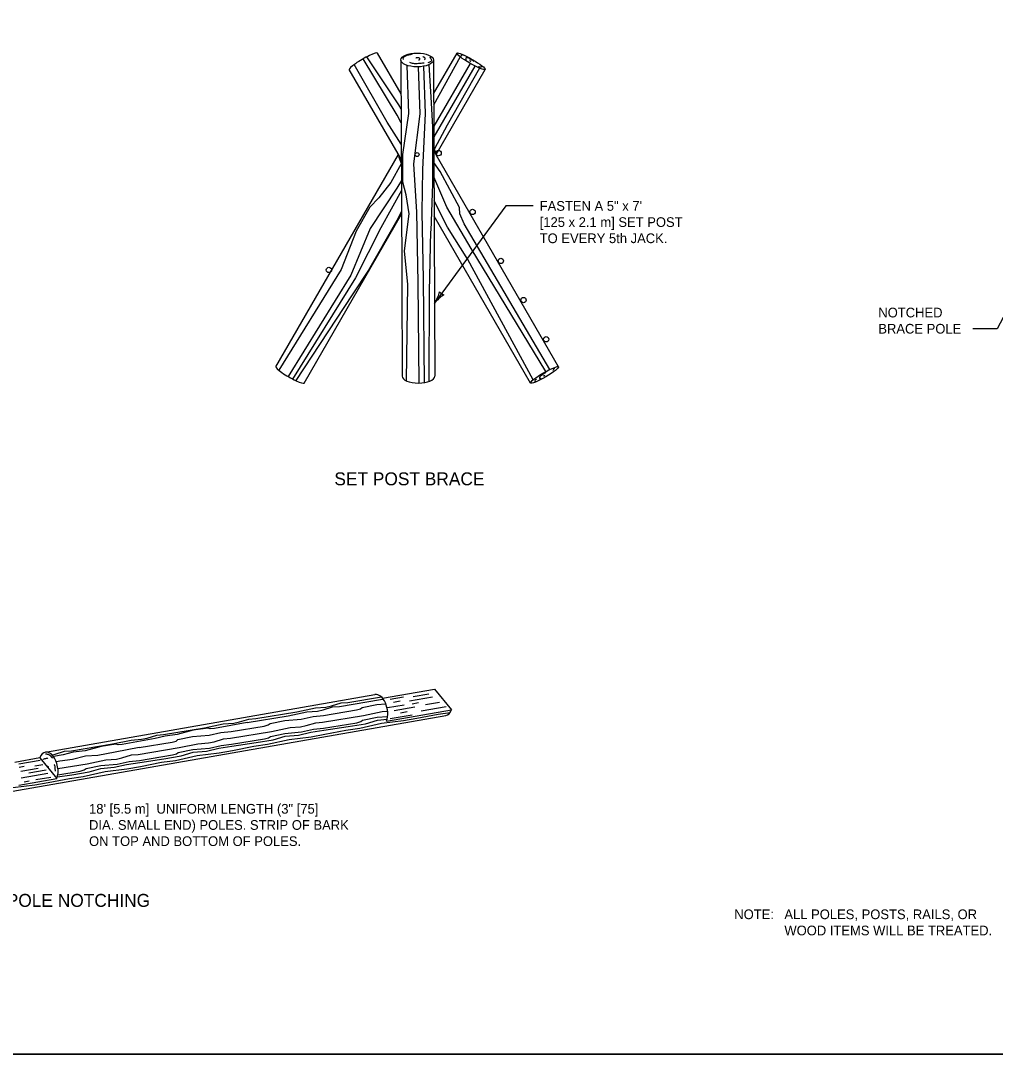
# Model space of a CAD drawing. Extents: x 49991.4 to 50021, y 49987.6 to 50011.4.
# Drawn here: x 50003.32 to 50009.35, y 49987.8 to 49994.19 of the extents above; entities that cross this region are included whole.
import ezdxf

# ---------------------------------------------------------------- set-up
doc = ezdxf.new("R2010")
doc.units = 0
for name, color, linetype in [('Level 1', 7, 'Continuous'), ('Level 2', 7, 'Continuous'), ('Level 3', 7, 'Continuous')]:
    doc.layers.add(name, color=color, linetype=linetype)

msp = doc.modelspace()

# ---------------------------------------------------------------- linework, layer by layer
at = {"layer": 'Level 1'}
for p, q in [((50005.6739, 49993.7368), (50005.5282, 49993.9891)), ((50005.875, 49993.737), (50006.0201, 49993.9885)), ((50005.6729, 49993.9457), (50005.6789, 49992.6324)), ((50005.874, 49993.9466), (50005.8788, 49992.8942)), ((50005.6557, 49993.3661), (50005.3543, 49993.8881)), ((50005.8904, 49993.3618), (50006.1944, 49993.8878)), ((50005.8766, 49993.3857), (50005.8933, 49993.3567)), ((50004.9005, 49992.049), (50005.6583, 49993.3616)), ((50005.6759, 49993.3309), (50005.6557, 49993.3661)), ((50006.6479, 49992.0498), (50005.8933, 49993.3567)), ((50005.0748, 49991.9487), (50005.6775, 49992.9928)), ((50006.474, 49991.9487), (50005.8784, 49992.9803)), ((50005.8785, 49992.8945), (50005.883, 49991.9911)), ((50005.6789, 49992.6324), (50005.6791, 49992.5534)), ((50005.6793, 49992.5688), (50005.6817, 49991.9911)), ((50003.4771, 49989.6671), (50005.5129, 49990.0228)), ((50005.5599, 49990.0012), (50005.8806, 49990.0572)), ((50005.6077, 49989.994), (50005.6902, 49990.0084)), ((50005.7266, 49989.9844), (50005.8681, 49990.0091)), ((50005.7483, 49990.0111), (50005.8449, 49990.028)), ((50005.8806, 49990.0572), (50005.9865, 49989.9297)), ((50005.5908, 49989.9425), (50005.6925, 49989.9603)), ((50005.6283, 49989.977), (50005.6688, 49989.984)), ((50005.6318, 49989.9254), (50005.7592, 49989.9476)), ((50005.7419, 49989.9667), (50005.7824, 49989.9738)), ((50005.7988, 49989.9229), (50005.9524, 49989.9497)), ((50005.8257, 49989.9616), (50005.9125, 49989.9768)), ((50000.9144, 49989.0139), (50005.951, 49989.8934)), ((50005.5849, 49989.8595), (50005.9865, 49989.9297)), ((50005.6076, 49989.8749), (50005.7433, 49989.8986)), ((50005.6714, 49989.9104), (50005.7118, 49989.9174)), ((50003.4416, 49989.6311), (50003.2869, 49989.6041)), ((50003.4436, 49989.6163), (50003.3119, 49989.5933)), ((50003.4416, 49989.6311), (50003.5478, 49989.5037)), ((50003.3445, 49989.5782), (50003.3151, 49989.5731)), ((50003.4314, 49989.5665), (50003.3243, 49989.5479)), ((50003.4812, 49989.5562), (50003.3745, 49989.5375)), ((50003.46, 49989.5896), (50003.411, 49989.5811)), ((50003.3119, 49989.4625), (50003.5478, 49989.5037)), ((50003.4907, 49989.5356), (50003.3277, 49989.5072)), ((50003.3757, 49989.4873), (50003.3464, 49989.4822)), ((50003.5108, 49989.5113), (50003.4181, 49989.4951))]:
    msp.add_line(p, q, dxfattribs=at)
msp.add_lwpolyline([(49999.3835, 49998.9992), (50016.7501, 49998.9992), (50016.7501, 49987.7988), (49999.3835, 49987.7988)], close=True, dxfattribs=at)
for points in [[(50005.6744, 49993.6448), (50005.6615, 49993.6702), (50005.4629, 49993.9662)], [(50006.0399, 49993.9658), (50005.8753, 49993.6669)], [(50005.6754, 49993.427), (50005.5886, 49993.5617), (50005.3837, 49993.9179)], [(50005.6748, 49993.5576), (50005.6504, 49993.6056), (50005.4401, 49993.9538)], [(50005.696, 49992.7666), (50005.7236, 49992.9951), (50005.7051, 49993.1132), (50005.6856, 49993.1918), (50005.6854, 49993.3619), (50005.7228, 49993.6147), (50005.7122, 49993.9129)], [(50005.7799, 49992.5686), (50005.7716, 49993.0065), (50005.7526, 49993.3054), (50005.7928, 49993.6145), (50005.7823, 49993.9043)], [(50005.8128, 49992.5913), (50005.8045, 49993.0062), (50005.8081, 49993.2697), (50005.8255, 49993.6148), (50005.8149, 49993.9079)], [(50005.8602, 49992.8906), (50005.8709, 49993.1807), (50005.871, 49993.5336), (50005.8605, 49993.7157), (50005.8476, 49993.9179)], [(50006.1021, 49993.9249), (50005.8759, 49993.537)], [(50006.1311, 49993.9091), (50005.8762, 49993.4717)], [(50006.1598, 49993.8956), (50005.9597, 49993.5429), (50005.8807, 49993.3964)], [(50005.6758, 49993.3047), (50005.6117, 49993.1883), (50005.5371, 49993.0949), (50005.4811, 49993.0362), (50005.3966, 49992.8886), (50005.3037, 49992.6506), (50004.9181, 49992.0285)], [(50006.5936, 49992.0328), (50006.0652, 49992.9326), (50006.0366, 49992.9963), (50006.0344, 49993.0354), (50005.9152, 49993.2571), (50005.8769, 49993.3119)], [(50005.6765, 49993.2023), (50005.6477, 49993.1544), (50005.4831, 49992.9044), (50005.3645, 49992.6161), (50004.9762, 49991.9895)], [(50006.5681, 49992.0195), (50006.107, 49992.782), (50005.9572, 49993.0356), (50005.8773, 49993.2241)], [(50005.6768, 49993.1391), (50005.5489, 49992.9078), (50005.3928, 49992.5995), (50005.0044, 49991.9738)], [(50006.4906, 49991.969), (50006.0865, 49992.7125), (50005.9612, 49992.9128), (50005.878, 49993.0767)], [(50005.6774, 49993.0111), (50005.6475, 49992.954), (50005.4726, 49992.6475), (50005.373, 49992.4946), (50005.0236, 49991.9641)], [(50005.8481, 49991.9593), (50005.8497, 49992.5145), (50005.8591, 49992.8883)], [(50005.7167, 49992.5577), (50005.696, 49992.7666)], [(50005.7074, 49991.9624), (50005.7167, 49992.5577)], [(50005.7855, 49991.9487), (50005.7799, 49992.5686)], [(50005.8183, 49991.9516), (50005.8128, 49992.5913)], [(50005.2935, 49989.9501), (50005.5467, 49989.9919), (50005.5643, 49989.9956)], [(50005.346, 49989.9745), (50005.5529, 49990.0086)], [(50004.724, 49989.8506), (50004.9771, 49989.8925), (50005.0923, 49989.9164), (50005.1577, 49989.9214), (50005.1923, 49989.9287), (50005.2511, 49989.9468), (50005.2935, 49989.9501)], [(50004.7765, 49989.8749), (50005.0296, 49989.9168), (50005.1448, 49989.9407), (50005.2101, 49989.9457), (50005.2448, 49989.953), (50005.3034, 49989.9711), (50005.346, 49989.9745)], [(50005.1942, 49989.8943), (50005.3984, 49989.9279), (50005.4231, 49989.9347), (50005.4345, 49989.9433), (50005.5246, 49989.9618), (50005.5801, 49989.9665)], [(50004.207, 49989.7756), (50004.4602, 49989.8173), (50004.5753, 49989.8414), (50004.6407, 49989.8463), (50004.6753, 49989.8535), (50004.7341, 49989.8717), (50004.7765, 49989.8749)], [(50004.6249, 49989.7949), (50004.8291, 49989.8285), (50004.8536, 49989.8354), (50004.8652, 49989.844), (50004.9553, 49989.8624), (50005.0576, 49989.871), (50005.1309, 49989.8878), (50005.1942, 49989.8943)], [(50005.1895, 49989.8524), (50005.4425, 49989.8942), (50005.5577, 49989.9181), (50005.5912, 49989.9207)], [(50005.1959, 49989.8153), (50005.4, 49989.8489), (50005.4248, 49989.8558), (50005.4362, 49989.8644), (50005.5264, 49989.8828), (50005.5913, 49989.8883)], [(50005.1981, 49989.8027), (50005.3481, 49989.8256), (50005.4544, 49989.8427), (50005.5281, 49989.865), (50005.5882, 49989.8705)], [(50005.2024, 49989.7773), (50005.3332, 49989.8034), (50005.4188, 49989.8152), (50005.5531, 49989.8456), (50005.6884, 49989.8622), (50005.7717, 49989.8768)], [(50005.7717, 49989.8768), (50005.9026, 49989.9029), (50005.9783, 49989.9132)], [(50004.724, 49989.8506), (50004.5206, 49989.8132), (50004.4949, 49989.8111), (50004.4814, 49989.8152), (50004.3903, 49989.802), (50004.2911, 49989.7756), (50004.2165, 49989.7665), (50004.1547, 49989.7511)], [(50004.6201, 49989.7529), (50004.8732, 49989.7946), (50004.9883, 49989.8187), (50005.0537, 49989.8236), (50005.0883, 49989.831), (50005.1472, 49989.849), (50005.1895, 49989.8524)], [(50004.6265, 49989.7158), (50004.8306, 49989.7494), (50004.8553, 49989.7563), (50004.8669, 49989.7648), (50004.957, 49989.7834), (50005.0592, 49989.792), (50005.1324, 49989.8088), (50005.1959, 49989.8153)], [(50004.1547, 49989.7511), (50003.9512, 49989.7136), (50003.9256, 49989.7116), (50003.9121, 49989.7157), (50003.821, 49989.7024), (50003.7218, 49989.676), (50003.6473, 49989.6668), (50003.5855, 49989.6515)], [(50003.6376, 49989.676), (50003.8907, 49989.7178), (50004.0059, 49989.7419), (50004.0712, 49989.7467), (50004.1059, 49989.7541), (50004.1646, 49989.7722), (50004.207, 49989.7756)], [(50004.0506, 49989.6533), (50004.3037, 49989.6952), (50004.4189, 49989.7192), (50004.4843, 49989.7241), (50004.519, 49989.7316), (50004.5777, 49989.7496), (50004.6201, 49989.7529)], [(50004.0556, 49989.6955), (50004.2597, 49989.729), (50004.2844, 49989.736), (50004.2958, 49989.7445), (50004.386, 49989.7631), (50004.4882, 49989.7717), (50004.5615, 49989.7884), (50004.6249, 49989.7949)], [(50004.6287, 49989.7032), (50004.7786, 49989.7261), (50004.885, 49989.7433), (50004.9588, 49989.7656), (50005.0409, 49989.773), (50005.117, 49989.7904), (50005.1981, 49989.8027)], [(50004.6331, 49989.6778), (50004.7639, 49989.7039), (50004.8495, 49989.7157), (50004.9838, 49989.7463), (50005.1189, 49989.7628), (50005.2024, 49989.7773)], [(50003.5179, 49989.6507), (50003.5365, 49989.6546), (50003.5952, 49989.6727), (50003.6376, 49989.676)], [(50004.0556, 49989.6955), (50003.9068, 49989.6661), (50003.801, 49989.6465), (50003.7241, 49989.6423), (50003.6442, 49989.6215), (50003.5667, 49989.612), (50003.5442, 49989.6075)], [(50004.0572, 49989.6163), (50004.2612, 49989.6499), (50004.286, 49989.6569), (50004.2975, 49989.6654), (50004.3876, 49989.6839), (50004.4898, 49989.6925), (50004.5631, 49989.7092), (50004.6265, 49989.7158)], [(50004.0594, 49989.6037), (50004.2093, 49989.6266), (50004.3157, 49989.6438), (50004.3894, 49989.666), (50004.4715, 49989.6737), (50004.5476, 49989.6909), (50004.6287, 49989.7032)], [(50004.0638, 49989.5784), (50004.1945, 49989.6044), (50004.2801, 49989.616), (50004.4144, 49989.6468), (50004.5496, 49989.6633), (50004.6331, 49989.6778)], [(50003.5855, 49989.6515), (50003.5265, 49989.6406)], [(50003.5536, 49989.5277), (50003.692, 49989.5505), (50003.7167, 49989.5574), (50003.7281, 49989.5659), (50003.8183, 49989.5844), (50003.9205, 49989.593), (50003.9938, 49989.6098), (50004.0572, 49989.6163)], [(50003.554, 49989.5659), (50003.7345, 49989.5958), (50003.8497, 49989.6197), (50003.915, 49989.6247), (50003.9496, 49989.6321), (50004.0083, 49989.6501), (50004.0506, 49989.6533)], [(50003.4943, 49989.4789), (50003.6251, 49989.505), (50003.7108, 49989.5167), (50003.8452, 49989.5473), (50003.9803, 49989.5639), (50004.0638, 49989.5784)], [(50003.5508, 49989.5135), (50003.6399, 49989.5271), (50003.7463, 49989.5444), (50003.8199, 49989.5665), (50003.9022, 49989.5743), (50003.9784, 49989.5914), (50004.0594, 49989.6037)], [(50002.925, 49989.3794), (50003.0558, 49989.4055), (50003.1413, 49989.4174), (50003.2756, 49989.4478), (50003.4108, 49989.4643), (50003.4943, 49989.4789)]]:
    msp.add_lwpolyline(points, dxfattribs=at)
for centre, radius in [((50005.9062, 49993.3707), 0.0165), ((50005.7735, 49993.3616), 0.012), ((50006.116, 49993.0071), 0.0165), ((50006.2909, 49992.7042), 0.0165), ((50005.2284, 49992.6483), 0.0165), ((50006.4309, 49992.4619), 0.0165), ((50006.5708, 49992.2195), 0.0165)]:
    msp.add_circle(centre, radius, dxfattribs=at)
for centre, major_axis, ratio, start_param, end_param in [((50005.4414, 49993.9383), (-0.087, -0.0505), 0.139914, 3.139201, 6.283242), ((50005.8294, 49993.4656), (-0.0603, 0.1046), 0.116361, 3.210167, 4.039569), ((50005.7192, 49993.2577), (-0.0603, 0.1046), 0.116361, 0.063126, 0.986139), ((50004.9877, 49991.9991), (-0.0871, 0.0503), 0.139914, 6.282865, 9.424578), ((50005.7815, 49991.9911), (-0.1006, 0), 0.422387, 0.000059, 3.141579), ((50005.5317, 49989.9231), (-0.0175, 0.0999), 0.577493, 3.925489, 6.306126), ((50005.9334, 49989.9932), (-0.0175, 0.0999), 0.577493, 3.141466, 3.926391), ((50003.4946, 49989.5672), (-0.0175, 0.0999), 0.577493, 3.925612, 7.06337)]:
    msp.add_ellipse(centre, major_axis=major_axis, ratio=ratio, start_param=start_param, end_param=end_param, dxfattribs=at)
for centre, major_axis, ratio in [((50005.7735, 49993.9466), (-0.1006, 0), 0.422387), ((50006.1072, 49993.9382), (-0.0871, 0.0503), 0.139914), ((50006.561, 49991.9993), (-0.087, -0.0505), 0.139914)]:
    msp.add_ellipse(centre, major_axis=major_axis, ratio=ratio, dxfattribs=at)
for points in [[(50005.7435, 49993.9825), (50005.7298, 49993.9785), (50005.7199, 49993.9771), (50005.7096, 49993.974), (50005.7011, 49993.9699), (50005.6945, 49993.9668), (50005.6902, 49993.9637), (50005.6864, 49993.9583), (50005.6864, 49993.952), (50005.6883, 49993.9493)], [(50005.7826, 49993.9484), (50005.7859, 49993.9484), (50005.7907, 49993.9538), (50005.7888, 49993.9574), (50005.7803, 49993.9601), (50005.7737, 49993.9601), (50005.7685, 49993.9596), (50005.7652, 49993.9574)], [(50005.819, 49993.9484), (50005.8213, 49993.9511), (50005.8222, 49993.9569), (50005.819, 49993.9619), (50005.8138, 49993.9637), (50005.8086, 49993.9668)], [(50005.8515, 49993.9637), (50005.8543, 49993.9614), (50005.8581, 49993.9552), (50005.8609, 49993.9498), (50005.8614, 49993.943), (50005.8581, 49993.9368), (50005.8496, 49993.9323), (50005.8406, 49993.9283)], [(50006.0625, 49993.974), (50006.0562, 49993.9771), (50006.0492, 49993.9791), (50006.0456, 49993.9778), (50006.0451, 49993.9765), (50006.0463, 49993.9727), (50006.0468, 49993.9715)], [(50006.1233, 49993.9376), (50006.1168, 49993.9428), (50006.1065, 49993.9488), (50006.0969, 49993.9548), (50006.0871, 49993.9597), (50006.0815, 49993.9611), (50006.0769, 49993.9605), (50006.0747, 49993.9584), (50006.0742, 49993.9556), (50006.0755, 49993.9533), (50006.0791, 49993.9493)], [(50005.8166, 49993.9278), (50005.8058, 49993.9265), (50005.7902, 49993.9247), (50005.7746, 49993.9233), (50005.7624, 49993.9229), (50005.7506, 49993.9242), (50005.7378, 49993.9265), (50005.7275, 49993.9301)], [(50006.1011, 49993.9433), (50006.0995, 49993.9437), (50006.0992, 49993.9428), (50006.1011, 49993.9404), (50006.1022, 49993.9394), (50006.1044, 49993.9375), (50006.1055, 49993.9377)], [(50006.1667, 49993.9067), (50006.1685, 49993.9047), (50006.1683, 49993.9025), (50006.1659, 49993.9011), (50006.1598, 49993.902), (50006.1522, 49993.9049)], [(50006.6155, 49992.0404), (50006.6181, 49992.0413), (50006.62, 49992.0402), (50006.6203, 49992.0375), (50006.6169, 49992.0322), (50006.6111, 49992.0265)], [(50006.5696, 49992.0137), (50006.562, 49992.0099), (50006.5523, 49992.0031), (50006.5428, 49991.9967), (50006.5343, 49991.9898), (50006.5308, 49991.9855), (50006.5294, 49991.9809), (50006.5305, 49991.9781), (50006.5329, 49991.9764), (50006.5355, 49991.9766), (50006.5406, 49991.9784)], [(50006.5551, 49991.9958), (50006.554, 49991.9945), (50006.5548, 49991.9938), (50006.5578, 49991.9946), (50006.5591, 49991.9953), (50006.5618, 49991.9965), (50006.562, 49991.9975)], [(50006.5111, 49991.9734), (50006.5057, 49991.9689), (50006.5011, 49991.9633), (50006.5007, 49991.9596), (50006.5018, 49991.9585), (50006.5057, 49991.9582), (50006.507, 49991.9581)], [(50003.4639, 49989.6219), (50003.4654, 49989.623), (50003.4727, 49989.6273), (50003.4801, 49989.6287), (50003.4865, 49989.6299), (50003.4924, 49989.6276)], [(50003.4777, 49989.6573), (50003.4836, 49989.6563), (50003.4912, 49989.6547), (50003.4955, 49989.6532), (50003.5003, 49989.6507), (50003.5036, 49989.6475), (50003.5068, 49989.6439), (50003.5117, 49989.6399), (50003.5133, 49989.6383), (50003.5155, 49989.6352), (50003.5176, 49989.6311), (50003.5182, 49989.6296)], [(50003.4834, 49989.5809), (50003.4835, 49989.5809), (50003.4836, 49989.581), (50003.4838, 49989.5812), (50003.4841, 49989.5813), (50003.4846, 49989.5815), (50003.4849, 49989.5816), (50003.4852, 49989.5816), (50003.4857, 49989.5816), (50003.486, 49989.5816), (50003.4863, 49989.5815), (50003.4866, 49989.5815), (50003.4869, 49989.5814), (50003.4874, 49989.5813), (50003.488, 49989.5812), (50003.4883, 49989.5811), (50003.4887, 49989.581), (50003.4894, 49989.5808), (50003.4901, 49989.5804), (50003.4904, 49989.5802), (50003.4906, 49989.58), (50003.4908, 49989.5799), (50003.4912, 49989.5795), (50003.4916, 49989.5791), (50003.4919, 49989.5787), (50003.492, 49989.5785), (50003.4922, 49989.5782), (50003.4924, 49989.5778), (50003.4926, 49989.5773), (50003.4927, 49989.5768), (50003.4928, 49989.5763), (50003.4929, 49989.5751), (50003.4929, 49989.5739), (50003.4929, 49989.5728), (50003.4928, 49989.5716), (50003.4928, 49989.5708), (50003.4927, 49989.5701), (50003.4927, 49989.5697)], [(50003.5385, 49989.5497), (50003.539, 49989.5543), (50003.5379, 49989.559), (50003.5364, 49989.5706), (50003.5362, 49989.5736), (50003.5355, 49989.5825), (50003.5318, 49989.5886)]]:
    msp.add_spline(points, degree=3, dxfattribs=at)
at = {"layer": 'Level 3'}
msp.add_line((49999.3835, 49987.7988), (50016.7501, 49987.7988), dxfattribs=at)
for points in [[(50006.4909, 49993.0442), (50006.3225, 49993.0442), (50005.8808, 49992.4428)], [(50009.5623, 49992.6696), (50009.3573, 49992.2849), (50009.2073, 49992.2849)]]:
    msp.add_lwpolyline(points, dxfattribs=at)
for centre, radius, start, end in [((50005.6864, 49992.5713), 0.233, 326.53196, 345.78181), ((50006.0544, 49992.3039), 0.2223, 121.16066, 141.34417), ((50005.9567, 49992.5461), 0.0548, 215.84347, 251.56583)]:
    msp.add_arc(centre, radius, start, end, dxfattribs=at)

# ---------------------------------------------------------------- texts
at = {"layer": 'Level 2'}
for s, height, p in [('FASTEN A 5" x 7\'', 0.06, (50006.5309, 49993.0142)), ('[125 x 2.1 m] SET POST', 0.06, (50006.5309, 49992.9142)), ('TO EVERY 5th JACK.', 0.06, (50006.5309, 49992.8142)), ('NOTCHED', 0.06, (50008.6232, 49992.3549)), ('BRACE POLE', 0.06, (50008.6232, 49992.2549)), ('SET POST BRACE', 0.08, (50005.2622, 49991.3169)), ('18\' [5.5 m]  UNIFORM LENGTH (3" [75]', 0.06, (50003.7463, 49989.2868)), ('DIA. SMALL END) POLES. STRIP OF BARK', 0.06, (50003.7463, 49989.1868)), ('ON TOP AND BOTTOM OF POLES.', 0.06, (50003.7463, 49989.0868)), ('BRACE POLE NOTCHING', 0.08, (50002.8396, 49988.7106)), ('NOTE: ', 0.06, (50007.7332, 49988.6345)), ('ALL POLES, POSTS, RAILS, OR', 0.06, (50008.0428, 49988.6345)), ('WOOD ITEMS WILL BE TREATED.', 0.06, (50008.0428, 49988.5345))]:
    msp.add_text(s, height=height, dxfattribs=at).set_placement(p)

doc.saveas('drawing.dxf')
